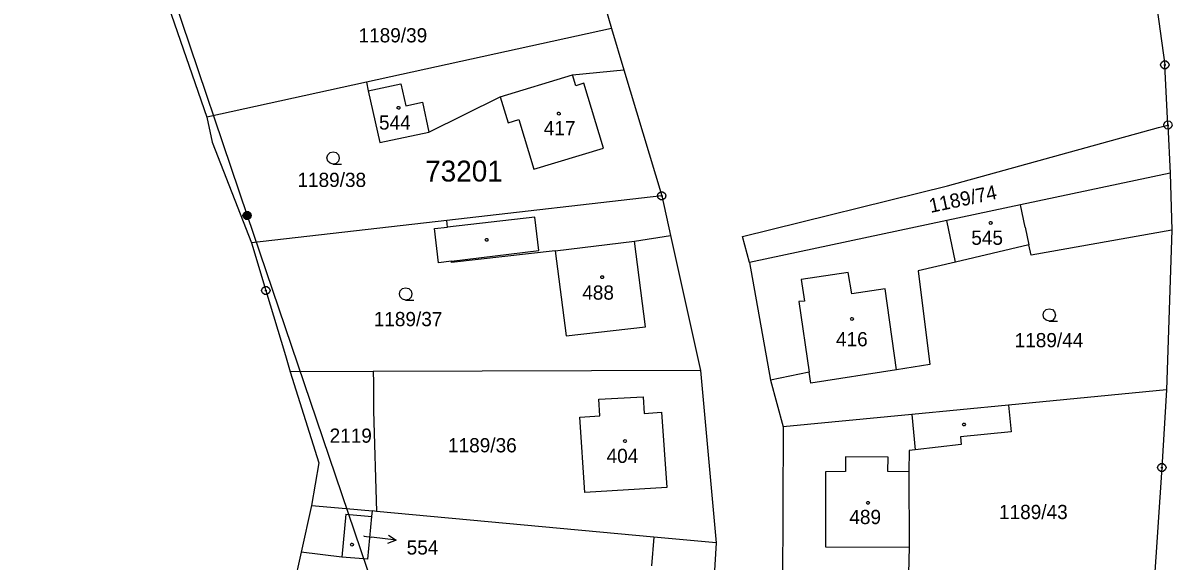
# Model space of a CAD drawing. Extents: x -789470 to -786707, y -1118640 to -1114455.
# Drawn here: x -787841.4 to -787703.9, y -1116573.1 to -1116508.7 of the extents above; entities that cross this region are included whole.
import ezdxf

# ---------------------------------------------------------------- set-up
doc = ezdxf.new("R2010")
doc.units = 0
for name, color, linetype in [('1', 7, 'Continuous'), ('11', 7, 'Continuous'), ('12', 7, 'Continuous'), ('2', 7, 'Continuous'), ('3', 7, 'Continuous'), ('4', 7, 'Continuous'), ('5', 7, 'Continuous'), ('6', 7, 'Continuous'), ('7', 7, 'Continuous'), ('8', 7, 'Continuous')]:
    doc.layers.add(name, color=color, linetype=linetype)

msp = doc.modelspace()

# ---------------------------------------------------------------- linework, layer by layer
at = {"layer": '1'}
for p, q in [((-787707.44, -1116494.38), (-787704.74, -1116513.73)), ((-787774.8, -1116496.28), (-787770.94, -1116509.39)), ((-787824.68, -1116504.6), (-787819.38, -1116520)), ((-787770.94, -1116509.39), (-787800.27, -1116515.81)), ((-787770.94, -1116509.39), (-787769.46, -1116514.31)), ((-787704.38, -1116520.92), (-787704.74, -1116513.73)), ((-787775.62, -1116514.93), (-787769.46, -1116514.31)), ((-787775.23, -1116516.22), (-787775.62, -1116514.93)), ((-787769.46, -1116514.31), (-787764.94, -1116529.41)), ((-787800.27, -1116515.81), (-787819.38, -1116520)), ((-787800.27, -1116515.81), (-787800.05, -1116516.84)), ((-787800.05, -1116516.84), (-787796.14, -1116515.98)), ((-787796.14, -1116515.98), (-787795.55, -1116518.64)), ((-787774.28, -1116515.93), (-787775.23, -1116516.22)), ((-787771.91, -1116523.69), (-787774.28, -1116515.93)), ((-787800.05, -1116516.84), (-787798.69, -1116523.02)), ((-787792.79, -1116521.76), (-787784.26, -1116517.54)), ((-787784.26, -1116517.54), (-787783.32, -1116520.65)), ((-787795.55, -1116518.64), (-787793.57, -1116518.2)), ((-787793.57, -1116518.2), (-787792.79, -1116521.76)), ((-787819.38, -1116520), (-787818.75, -1116522.97)), ((-787783.32, -1116520.65), (-787782.02, -1116520.26)), ((-787782.02, -1116520.26), (-787780.23, -1116526.19)), ((-787798.69, -1116523.02), (-787792.79, -1116521.76)), ((-787730.74, -1116528.21), (-787705.48, -1116521.22)), ((-787705.48, -1116521.22), (-787704.38, -1116520.92)), ((-787704.38, -1116520.92), (-787704.1, -1116526.68)), ((-787818.75, -1116522.97), (-787814.01, -1116535.01)), ((-787780.23, -1116526.19), (-787771.91, -1116523.69)), ((-787704.1, -1116526.68), (-787722.02, -1116530.48)), ((-787704.1, -1116526.68), (-787703.91, -1116533.48)), ((-787755.27, -1116534.26), (-787730.74, -1116528.21)), ((-787764.94, -1116529.41), (-787790.66, -1116532.35)), ((-787764.94, -1116529.41), (-787763.9, -1116534.13)), ((-787722.02, -1116530.48), (-787730.84, -1116532.35)), ((-787790.66, -1116532.35), (-787814.01, -1116535.01)), ((-787792.14, -1116533.29), (-787790.57, -1116533.12)), ((-787790.57, -1116533.12), (-787790.66, -1116532.35)), ((-787730.84, -1116532.35), (-787754.45, -1116537.36)), ((-787729.78, -1116537.32), (-787730.84, -1116532.35)), ((-787791.67, -1116537.39), (-787792.14, -1116533.29)), ((-787768.19, -1116534.8), (-787763.9, -1116534.13)), ((-787763.9, -1116534.13), (-787760.31, -1116550.28)), ((-787754.45, -1116537.36), (-787755.27, -1116534.26)), ((-787703.91, -1116533.48), (-787720.75, -1116536.47)), ((-787703.91, -1116533.48), (-787704.56, -1116552.61)), ((-787814.01, -1116535.01), (-787812.3, -1116540.72)), ((-787766.9, -1116545.04), (-787768.19, -1116534.8)), ((-787721.01, -1116535.26), (-787729.78, -1116537.32)), ((-787720.75, -1116536.47), (-787721.01, -1116535.26)), ((-787790.11, -1116537.21), (-787791.67, -1116537.39)), ((-787790.09, -1116537.35), (-787790.11, -1116537.21)), ((-787777.71, -1116535.98), (-787790.09, -1116537.35)), ((-787777.71, -1116535.98), (-787776.37, -1116546.13)), ((-787754.45, -1116537.36), (-787751.94, -1116551.42)), ((-787729.78, -1116537.32), (-787734.24, -1116538.36)), ((-787734.24, -1116538.36), (-787732.87, -1116549.58)), ((-787812.3, -1116540.72), (-787809.97, -1116548.49)), ((-787776.37, -1116546.13), (-787766.9, -1116545.04)), ((-787809.97, -1116548.49), (-787809.38, -1116550.45)), ((-787732.87, -1116549.58), (-787736.85, -1116550.2)), ((-787799.45, -1116550.42), (-787809.38, -1116550.45)), ((-787809.38, -1116550.45), (-787805.96, -1116561.31)), ((-787760.31, -1116550.28), (-787799.45, -1116550.42)), ((-787799.45, -1116550.42), (-787799.44, -1116551.72)), ((-787760.31, -1116550.28), (-787758.43, -1116570.89)), ((-787747.28, -1116550.47), (-787751.94, -1116551.42)), ((-787747.09, -1116551.78), (-787747.28, -1116550.47)), ((-787736.85, -1116550.2), (-787747.09, -1116551.78)), ((-787799.44, -1116551.72), (-787799.43, -1116555.12)), ((-787751.94, -1116551.42), (-787750.4, -1116557.03)), ((-787772.47, -1116553.72), (-787767.16, -1116553.44)), ((-787772.34, -1116555.7), (-787772.47, -1116553.72)), ((-787767.16, -1116553.44), (-787767.04, -1116555.41)), ((-787704.56, -1116552.61), (-787723.43, -1116554.43)), ((-787704.56, -1116552.61), (-787705.09, -1116561.9)), ((-787799.43, -1116555.12), (-787799.07, -1116567.13)), ((-787723.43, -1116554.43), (-787735.01, -1116555.55)), ((-787723.43, -1116554.43), (-787723.12, -1116557.61)), ((-787774.72, -1116555.86), (-787772.34, -1116555.7)), ((-787774.14, -1116564.87), (-787774.72, -1116555.86)), ((-787767.04, -1116555.41), (-787764.96, -1116555.28)), ((-787764.96, -1116555.28), (-787764.34, -1116564.26)), ((-787735.01, -1116555.55), (-787750.4, -1116557.03)), ((-787750.4, -1116557.03), (-787750.49, -1116577.34)), ((-787723.12, -1116557.61), (-787729.2, -1116558.2)), ((-787729.11, -1116559.14), (-787734.61, -1116559.75)), ((-787729.2, -1116558.2), (-787729.11, -1116559.14)), ((-787735.34, -1116559.83), (-787735.39, -1116562.39)), ((-787734.61, -1116559.75), (-787735.34, -1116559.83)), ((-787805.96, -1116561.31), (-787806.86, -1116566.41)), ((-787705.09, -1116561.9), (-787706.23, -1116578.86)), ((-787735.39, -1116562.39), (-787735.33, -1116571.39)), ((-787764.34, -1116564.26), (-787774.14, -1116564.87)), ((-787806.86, -1116566.41), (-787808.09, -1116572.02)), ((-787806.86, -1116566.41), (-787802.69, -1116566.8)), ((-787802.69, -1116566.8), (-787799.56, -1116567.08)), ((-787799.63, -1116567.76), (-787799.56, -1116567.08)), ((-787799.07, -1116567.13), (-787799.56, -1116567.08)), ((-787765.88, -1116570.2), (-787799.07, -1116567.13)), ((-787800.1, -1116572.86), (-787799.63, -1116567.76)), ((-787765.88, -1116570.2), (-787766.18, -1116573.66)), ((-787758.43, -1116570.89), (-787765.88, -1116570.2)), ((-787758.43, -1116570.89), (-787759.04, -1116580.87)), ((-787735.33, -1116571.39), (-787735.49, -1116577.85)), ((-787808.09, -1116572.02), (-787809.3, -1116577.54)), ((-787803.23, -1116572.59), (-787808.09, -1116572.02)), ((-787800.1, -1116572.86), (-787803.23, -1116572.59))]:
    msp.add_line(p, q, dxfattribs=at)
at = {"layer": '12'}
for p, q in [((-787784.26, -1116517.54), (-787775.62, -1116514.93)), ((-787775.23, -1116516.22), (-787775.62, -1116514.93)), ((-787800.05, -1116516.84), (-787796.14, -1116515.98)), ((-787796.14, -1116515.98), (-787795.55, -1116518.64)), ((-787774.28, -1116515.93), (-787775.23, -1116516.22)), ((-787771.91, -1116523.69), (-787774.28, -1116515.93)), ((-787800.05, -1116516.84), (-787798.69, -1116523.02)), ((-787784.26, -1116517.54), (-787783.32, -1116520.65)), ((-787795.55, -1116518.64), (-787793.57, -1116518.2)), ((-787793.57, -1116518.2), (-787792.79, -1116521.76)), ((-787783.32, -1116520.65), (-787782.02, -1116520.26)), ((-787782.02, -1116520.26), (-787780.23, -1116526.19)), ((-787798.69, -1116523.02), (-787792.79, -1116521.76)), ((-787780.23, -1116526.19), (-787771.91, -1116523.69)), ((-787722.02, -1116530.48), (-787730.84, -1116532.35)), ((-787721.46, -1116533.12), (-787722.02, -1116530.48)), ((-787729.78, -1116537.32), (-787730.84, -1116532.35)), ((-787721.46, -1116533.12), (-787721.01, -1116535.26)), ((-787777.71, -1116535.98), (-787768.19, -1116534.8)), ((-787766.9, -1116545.04), (-787768.19, -1116534.8)), ((-787721.01, -1116535.26), (-787729.78, -1116537.32)), ((-787777.71, -1116535.98), (-787776.37, -1116546.13)), ((-787742.63, -1116538.57), (-787748.25, -1116539.4)), ((-787742.21, -1116541.11), (-787742.63, -1116538.57)), ((-787748.25, -1116539.4), (-787747.86, -1116541.97)), ((-787738.19, -1116540.51), (-787742.21, -1116541.11)), ((-787736.85, -1116550.2), (-787738.19, -1116540.51)), ((-787747.86, -1116541.97), (-787748.53, -1116542.01)), ((-787748.53, -1116542.01), (-787747.28, -1116550.47)), ((-787776.37, -1116546.13), (-787766.9, -1116545.04)), ((-787747.09, -1116551.78), (-787747.28, -1116550.47)), ((-787736.85, -1116550.2), (-787747.09, -1116551.78)), ((-787772.47, -1116553.72), (-787767.16, -1116553.44)), ((-787772.34, -1116555.7), (-787772.47, -1116553.72)), ((-787767.16, -1116553.44), (-787767.04, -1116555.41)), ((-787774.72, -1116555.86), (-787772.34, -1116555.7)), ((-787774.14, -1116564.87), (-787774.72, -1116555.86)), ((-787767.04, -1116555.41), (-787764.96, -1116555.28)), ((-787764.96, -1116555.28), (-787764.34, -1116564.26)), ((-787742.94, -1116560.59), (-787742.96, -1116562.36)), ((-787737.86, -1116560.66), (-787742.94, -1116560.59)), ((-787737.88, -1116562.37), (-787737.86, -1116560.66)), ((-787742.96, -1116562.36), (-787745.35, -1116562.41)), ((-787745.35, -1116562.41), (-787745.35, -1116571.36)), ((-787735.39, -1116562.39), (-787737.88, -1116562.37)), ((-787735.39, -1116562.39), (-787735.33, -1116571.39)), ((-787764.34, -1116564.26), (-787774.14, -1116564.87)), ((-787802.75, -1116567.47), (-787803.23, -1116572.59)), ((-787802.75, -1116567.47), (-787799.63, -1116567.76)), ((-787800.1, -1116572.86), (-787799.63, -1116567.76)), ((-787745.35, -1116571.36), (-787735.33, -1116571.39)), ((-787800.1, -1116572.86), (-787803.23, -1116572.59))]:
    msp.add_line(p, q, dxfattribs=at)
at = {"layer": '3'}
for points in [[(-787804.25, -1116525.6), (-787804.63, -1116525.5), (-787804.9, -1116525.23), (-787805, -1116524.86), (-787804.9, -1116524.49), (-787804.63, -1116524.22), (-787804.26, -1116524.12), (-787803.89, -1116524.22), (-787803.62, -1116524.49), (-787803.52, -1116524.87), (-787803.62, -1116525.25), (-787803.89, -1116525.52), (-787804.27, -1116525.62), (-787803.27, -1116525.62)], [(-787795.57, -1116541.86), (-787795.95, -1116541.76), (-787796.22, -1116541.49), (-787796.32, -1116541.12), (-787796.22, -1116540.75), (-787795.95, -1116540.48), (-787795.58, -1116540.38), (-787795.21, -1116540.48), (-787794.94, -1116540.75), (-787794.84, -1116541.13), (-787794.94, -1116541.51), (-787795.21, -1116541.78), (-787795.59, -1116541.88), (-787794.59, -1116541.88)], [(-787718.56, -1116544.38), (-787718.94, -1116544.28), (-787719.21, -1116544.01), (-787719.31, -1116543.64), (-787719.21, -1116543.27), (-787718.94, -1116543), (-787718.57, -1116542.9), (-787718.2, -1116543), (-787717.93, -1116543.27), (-787717.83, -1116543.65), (-787717.93, -1116544.03), (-787718.2, -1116544.3), (-787718.58, -1116544.4), (-787717.58, -1116544.4)]]:
    msp.add_lwpolyline(points, dxfattribs=at)
at = {"layer": '4'}
for p, q in [((-787784.26, -1116517.54), (-787775.62, -1116514.93)), ((-787721.46, -1116533.12), (-787722.02, -1116530.48)), ((-787780.12, -1116531.94), (-787790.57, -1116533.12)), ((-787779.66, -1116535.91), (-787780.12, -1116531.94)), ((-787721.46, -1116533.12), (-787721.01, -1116535.26)), ((-787777.71, -1116535.98), (-787768.19, -1116534.8)), ((-787790.11, -1116537.21), (-787779.66, -1116535.91)), ((-787742.63, -1116538.57), (-787748.25, -1116539.4)), ((-787742.21, -1116541.11), (-787742.63, -1116538.57)), ((-787748.25, -1116539.4), (-787747.86, -1116541.97)), ((-787738.19, -1116540.51), (-787742.21, -1116541.11)), ((-787736.85, -1116550.2), (-787738.19, -1116540.51)), ((-787747.86, -1116541.97), (-787748.53, -1116542.01)), ((-787748.53, -1116542.01), (-787747.28, -1116550.47)), ((-787735.01, -1116555.55), (-787734.61, -1116559.75)), ((-787742.94, -1116560.59), (-787742.96, -1116562.36)), ((-787737.86, -1116560.66), (-787742.94, -1116560.59)), ((-787737.88, -1116562.37), (-787737.86, -1116560.66)), ((-787742.96, -1116562.36), (-787745.35, -1116562.41)), ((-787745.35, -1116562.41), (-787745.35, -1116571.36)), ((-787735.39, -1116562.39), (-787737.88, -1116562.37)), ((-787802.75, -1116567.47), (-787803.23, -1116572.59)), ((-787802.75, -1116567.47), (-787799.63, -1116567.76)), ((-787745.35, -1116571.36), (-787735.33, -1116571.39))]:
    msp.add_line(p, q, dxfattribs=at)
at = {"layer": '5'}
for points in [[(-787796.43, -1116518.69), (-787796.33, -1116518.71), (-787796.28, -1116518.8), (-787796.26, -1116518.86), (-787796.28, -1116518.95), (-787796.36, -1116519.02), (-787796.43, -1116519.03), (-787796.52, -1116519), (-787796.58, -1116518.94), (-787796.6, -1116518.86), (-787796.58, -1116518.77), (-787796.5, -1116518.7)], [(-787777.26, -1116519.39), (-787777.16, -1116519.41), (-787777.11, -1116519.5), (-787777.09, -1116519.56), (-787777.11, -1116519.65), (-787777.19, -1116519.72), (-787777.26, -1116519.73), (-787777.35, -1116519.7), (-787777.41, -1116519.64), (-787777.43, -1116519.56), (-787777.41, -1116519.47), (-787777.33, -1116519.4)], [(-787725.58, -1116532.46), (-787725.48, -1116532.48), (-787725.43, -1116532.57), (-787725.41, -1116532.63), (-787725.43, -1116532.72), (-787725.51, -1116532.79), (-787725.58, -1116532.8), (-787725.67, -1116532.77), (-787725.73, -1116532.71), (-787725.75, -1116532.63), (-787725.73, -1116532.54), (-787725.65, -1116532.47)], [(-787785.81, -1116534.51), (-787785.72, -1116534.66), (-787785.81, -1116534.81), (-787785.99, -1116534.81), (-787786.08, -1116534.66), (-787785.99, -1116534.51)], [(-787772.07, -1116538.95), (-787771.97, -1116538.97), (-787771.92, -1116539.06), (-787771.9, -1116539.12), (-787771.92, -1116539.21), (-787772, -1116539.28), (-787772.07, -1116539.29), (-787772.16, -1116539.26), (-787772.22, -1116539.2), (-787772.24, -1116539.12), (-787772.22, -1116539.03), (-787772.14, -1116538.96)], [(-787742.18, -1116543.95), (-787742.08, -1116543.97), (-787742.03, -1116544.06), (-787742.01, -1116544.12), (-787742.03, -1116544.21), (-787742.11, -1116544.28), (-787742.18, -1116544.29), (-787742.27, -1116544.26), (-787742.33, -1116544.2), (-787742.35, -1116544.12), (-787742.33, -1116544.03), (-787742.25, -1116543.96)], [(-787728.7, -1116556.59), (-787728.61, -1116556.74), (-787728.7, -1116556.89), (-787728.88, -1116556.89), (-787728.97, -1116556.74), (-787728.88, -1116556.59)], [(-787769.33, -1116558.55), (-787769.23, -1116558.57), (-787769.18, -1116558.66), (-787769.16, -1116558.72), (-787769.18, -1116558.81), (-787769.26, -1116558.88), (-787769.33, -1116558.89), (-787769.42, -1116558.86), (-787769.48, -1116558.8), (-787769.5, -1116558.72), (-787769.48, -1116558.63), (-787769.4, -1116558.56)], [(-787740.26, -1116565.94), (-787740.16, -1116565.96), (-787740.11, -1116566.05), (-787740.09, -1116566.11), (-787740.11, -1116566.2), (-787740.19, -1116566.27), (-787740.26, -1116566.28), (-787740.35, -1116566.25), (-787740.41, -1116566.19), (-787740.43, -1116566.11), (-787740.41, -1116566.02), (-787740.33, -1116565.95)], [(-787802.01, -1116570.94), (-787801.91, -1116570.96), (-787801.86, -1116571.05), (-787801.84, -1116571.11), (-787801.86, -1116571.2), (-787801.94, -1116571.27), (-787802.01, -1116571.28), (-787802.1, -1116571.25), (-787802.16, -1116571.19), (-787802.18, -1116571.11), (-787802.16, -1116571.02), (-787802.08, -1116570.95)]]:
    msp.add_lwpolyline(points, close=True, dxfattribs=at)
at = {"layer": '6'}
for p, q in [((-787841.37, -1116452.11), (-787814.56, -1116531.75)), ((-787814.56, -1116531.75), (-787782.31, -1116626.62))]:
    msp.add_line(p, q, dxfattribs=at)
msp.add_lwpolyline([(-787814.71, -1116531.27), (-787814.4, -1116531.27), (-787814.15, -1116531.45), (-787814.05, -1116531.74), (-787814.15, -1116532.03), (-787814.4, -1116532.21), (-787814.71, -1116532.21), (-787814.96, -1116532.03), (-787815.06, -1116531.74), (-787814.96, -1116531.45), (-787814.71, -1116531.27), (-787814.68, -1116531.31), (-787814.44, -1116531.31), (-787814.28, -1116531.39), (-787814.84, -1116531.39), (-787814.92, -1116531.47), (-787814.2, -1116531.47), (-787814.2, -1116531.55), (-787814.92, -1116531.55), (-787814.96, -1116531.63), (-787814.16, -1116531.63), (-787814.12, -1116531.71), (-787815, -1116531.71), (-787815, -1116531.79), (-787814.12, -1116531.79), (-787814.15, -1116531.87), (-787814.96, -1116531.87), (-787814.95, -1116531.95), (-787814.14, -1116531.95), (-787814.19, -1116532.03), (-787814.91, -1116532.03), (-787814.83, -1116532.11), (-787814.27, -1116532.11), (-787814.38, -1116532.19), (-787814.72, -1116532.19)], dxfattribs=at)
at = {"layer": '7'}
for p in [(-787800.56, -1116570.1), (-787796.7, -1116570.59)]:
    msp.add_line(p, (-787799.68, -1116570.21), dxfattribs=at)
msp.add_lwpolyline([(-787797.63, -1116569.97), (-787796.7, -1116570.59), (-787797.76, -1116570.96)], dxfattribs=at)
at = {"layer": '8'}
for p, q in [((-787704.86, -1116513.73), (-787704.62, -1116513.73)), ((-787704.4, -1116520.8), (-787704.36, -1116521.04)), ((-787765.06, -1116529.41), (-787764.82, -1116529.41)), ((-787812.42, -1116540.72), (-787812.18, -1116540.72)), ((-787705.21, -1116561.9), (-787704.97, -1116561.9))]:
    msp.add_line(p, q, dxfattribs=at)
for points in [[(-787704.59, -1116513.25), (-787704.34, -1116513.43), (-787704.24, -1116513.72), (-787704.34, -1116514.01), (-787704.59, -1116514.19), (-787704.9, -1116514.19), (-787705.15, -1116514.01), (-787705.25, -1116513.72), (-787705.15, -1116513.43), (-787704.9, -1116513.25)], [(-787703.88, -1116520.98), (-787704.01, -1116521.26), (-787704.28, -1116521.41), (-787704.58, -1116521.36), (-787704.81, -1116521.15), (-787704.86, -1116520.84), (-787704.73, -1116520.57), (-787704.46, -1116520.42), (-787704.16, -1116520.46), (-787703.94, -1116520.68)], [(-787764.79, -1116528.93), (-787764.54, -1116529.11), (-787764.44, -1116529.4), (-787764.54, -1116529.69), (-787764.79, -1116529.87), (-787765.1, -1116529.87), (-787765.35, -1116529.69), (-787765.45, -1116529.4), (-787765.35, -1116529.11), (-787765.1, -1116528.93)], [(-787812.15, -1116540.24), (-787811.9, -1116540.42), (-787811.8, -1116540.71), (-787811.9, -1116541), (-787812.15, -1116541.18), (-787812.46, -1116541.18), (-787812.71, -1116541), (-787812.81, -1116540.71), (-787812.71, -1116540.42), (-787812.46, -1116540.24)], [(-787704.94, -1116561.42), (-787704.69, -1116561.6), (-787704.59, -1116561.89), (-787704.69, -1116562.18), (-787704.94, -1116562.36), (-787705.25, -1116562.36), (-787705.5, -1116562.18), (-787705.6, -1116561.89), (-787705.5, -1116561.6), (-787705.25, -1116561.42)]]:
    msp.add_lwpolyline(points, close=True, dxfattribs=at)

# ---------------------------------------------------------------- texts
at = {"layer": '11'}
msp.add_text('73201', height=2.5, dxfattribs=at).set_placement((-787793.25, -1116527.68))
at = {"layer": '2'}
for s, height, p in [('1189/39', 1.7, (-787801.22, -1116511.04)), ('544', 1.7, (-787798.77, -1116521.47)), ('417', 1.7, (-787779.05, -1116522.14)), ('1189/38', 1.7, (-787808.53, -1116528.33)), ('545', 1.7, (-787727.9, -1116535.25)), ('488', 1.7, (-787774.45, -1116541.81)), ('1189/37', 1.7, (-787799.4, -1116544.98)), ('416', 1.7, (-787744.09, -1116547.39)), ('1189/44', 1.7, (-787722.71, -1116547.5)), ('2119', 1.7, (-787804.68, -1116558.92)), ('1189/36', 1.7, (-787790.51, -1116560.07)), ('404', 1.7, (-787771.54, -1116561.34)), ('489', 1.7, (-787742.49, -1116568.65)), ('1189/43', 1.7, (-787724.58, -1116568.05)), ('554', 0.1, (-787800.68, -1116570.1))]:
    msp.add_text(s, height=height, dxfattribs=at).set_placement(p)
msp.add_text('1189/74', height=1.7, rotation=11.9748, dxfattribs=at).set_placement((-787732.76, -1116531.44))
at = {"layer": '7'}
msp.add_text('554', height=1.7, dxfattribs=at).set_placement((-787795.46, -1116572.29))

doc.saveas('drawing.dxf')
